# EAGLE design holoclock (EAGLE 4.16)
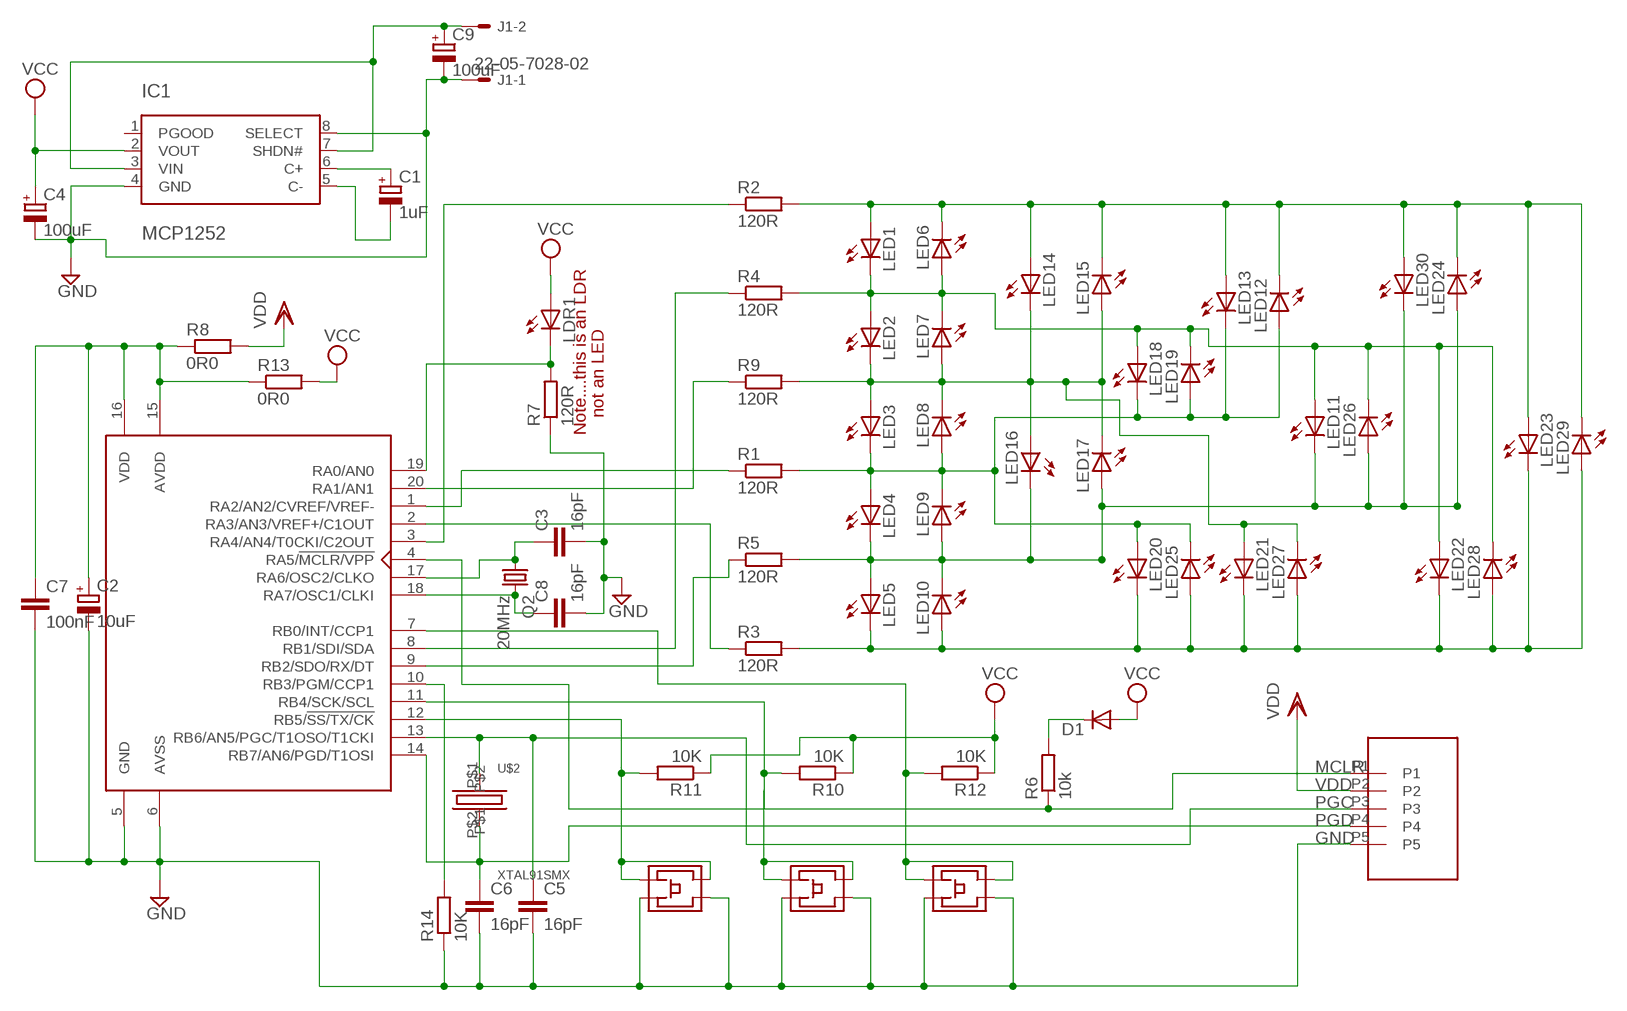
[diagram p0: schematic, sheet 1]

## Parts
C1  1uF  CPOL-EUSMCA  [SMC_A]
C2  10uF  CPOL-EUCT3528  [CT3528]
C3  16pF  C-EUC0805K  [C0805K]
C4  100uF  CPOL-EUSMCD  [SMC_D]
C5  16pF  C-EUC0805K  [C0805K]
C6  16pF  C-EUC0805K  [C0805K]
C7  100nF  C-EUC0805K  [C0805K]
C8  16pF  C-EUC0805K  [C0805K]
C9  100uF  CPOL-EUSMCD  [SMC_D]
D1  DIODE-MINIMELF  [MINIMELF]
IC1  MCP1252  [MSOP8]
J1  22-05-7028-02  [7395-02]
LDR1  LED5MM  [LED5MM]
LED1  LEDSMT1206  [1206]
LED2  LEDSMT1206  [1206]
LED3  LEDSMT1206  [1206]
LED4  LEDSMT1206  [1206]
LED5  LEDSMT1206  [1206]
LED6  LEDSMT1206  [1206]
LED7  LEDSMT1206  [1206]
LED8  LEDSMT1206  [1206]
LED9  LEDSMT1206  [1206]
LED10  LEDSMT1206  [1206]
LED11  LEDSMT1206  [1206]
LED12  LEDSMT1206  [1206]
LED13  LEDSMT1206  [1206]
LED14  LEDSMT1206  [1206]
LED15  LEDSMT1206  [1206]
LED16  LEDSMT1206  [1206]
LED17  LEDSMT1206  [1206]
LED18  LEDSMT1206  [1206]
LED19  LEDSMT1206  [1206]
LED20  LEDSMT1206  [1206]
LED21  LEDSMT1206  [1206]
LED22  LEDSMT1206  [1206]
LED23  LEDSMT1206  [1206]
LED24  LEDSMT1206  [1206]
LED25  LEDSMT1206  [1206]
LED26  LEDSMT1206  [1206]
LED27  LEDSMT1206  [1206]
LED28  LEDSMT1206  [1206]
LED29  LEDSMT1206  [1206]
LED30  LEDSMT1206  [1206]
Q2  20MHz  CRYSTALHC49UP  [HC49UP]
R1  120R  R-EU_M0805  [M0805]
R2  120R  R-EU_M0805  [M0805]
R3  120R  R-EU_M0805  [M0805]
R4  120R  R-EU_M0805  [M0805]
R5  120R  R-EU_M0805  [M0805]
R6  10k  R-EU_M0805  [M0805]
R7  120R  R-EU_M0805  [M0805]
R8  0R0  R-EU_M0805  [M0805]
R9  120R  R-EU_M0805  [M0805]
R10  10K  R-EU_M0805  [M0805]
R11  10K  R-EU_M0805  [M0805]
R12  10K  R-EU_M0805  [M0805]
R13  0R0  R-EU_M0805  [M0805]
R14  10K  R-EU_M0805  [M0805]
SW1  SMDMICROSWITCH  [SMDMICROSWITCH]
SW2  SMDMICROSWITCH  [SMDMICROSWITCH]
SW3  SMDMICROSWITCH  [SMDMICROSWITCH]
U$1  MATE-N-LOK-5WAY  [MATE-N-LOK-5WAY]
U$2  XTAL91SMX  [XTAL91SMX]
U$6  16F88SOIP20  [SSOP20]

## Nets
GND: C2.- C3.2 C4.- C5.2 C6.2 C7.2 C8.2 C9.- IC1.4(GND) IC1.8(SELECT) J1.1 R7.1 R14.1 SW1.L1 SW1.R1 SW2.L1 SW2.R1 SW3.L1 SW3.R1 U$1.P5 U$6.5(GND) U$6.6(AVSS)
LDR1: LDR1.K(C) R7.2 U$6.19(RA0/AN0)
MCLR: R6.1 U$1.P1 U$6.4(RA5/!MCLR/VPP)
N$1: C8.1 Q2.2 U$6.18(RA7/OSC1/CLKI)
N$2: R2.1 U$6.3(RA4/AN4/T0CKI/C2OUT)
N$3: C3.1 Q2.1 U$6.17(RA6/OSC2/CLKO)
N$4: C9.+ IC1.3(VIN) IC1.7(SHDN#) J1.2
N$5: R3.1 U$6.2(RA3/AN3/VREF+/C1OUT)
N$6: R1.1 U$6.1(RA2/AN2/CVREF/VREF-)
N$7: R14.2 U$6.10(RB3/PGM/CCP1)
N$8: R10.2 SW1.L2 SW1.R2 U$6.11(RB4/SCK/SCL)
N$9: D1.C R6.2
N$10: C1.+ IC1.6(C+)
N$11: C1.- IC1.5(C-)
N$13: R11.2 SW3.L2 SW3.R2 U$6.12(RB5/!SS/TX/CK)
N$17: R5.1 U$6.9(RB2/SDO/RX/DT)
N$20: R9.1 U$6.20(RA1/AN1)
N$21: R4.1 U$6.8(RB1/SDI/SDA)
N$23: R12.2 SW2.L2 SW2.R2 U$6.7(RB0/INT/CCP1)
PGC: C5.1 U$1.P3 U$2.P$1 U$6.13(RB6/AN5/PGC/T1OSO/T1CKI)
PGD: C6.1 U$1.P4 U$2.P$2 U$6.14(RB7/AN6/PGD/T1OSI)
PWRCPU: C2.+ C7.1 R8.1 R13.1 U$6.15(AVDD) U$6.16(VDD)
R1: LED1.A LED6.C LED12.C LED13.A LED14.A LED15.C LED23.A LED24.C LED29.C LED30.A R2.2
R2: LED1.C LED2.A LED6.A LED7.C LED11.A LED18.A LED19.C LED22.A LED26.C LED28.C R4.2
R3: LED2.C LED3.A LED7.A LED8.C LED14.C LED15.A LED16.A LED17.C LED21.A LED27.C R9.2
R4: LED3.C LED4.A LED8.A LED9.C LED12.A LED13.C LED18.C LED19.A LED20.A LED25.C R1.2
R5: LED4.C LED5.A LED9.A LED10.C LED11.C LED16.C LED17.A LED24.A LED26.A LED30.C R5.2
R6: LED5.C LED10.A LED20.C LED21.C LED22.C LED23.C LED25.A LED27.A LED28.A LED29.A R3.2
VCC: C4.+ D1.A IC1.2(VOUT) LDR1.A R10.1 R11.1 R12.1 R13.2
VDD: R8.2 U$1.P2
Unconnected: IC1.1(PGOOD)

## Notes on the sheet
- not an LED
- Note....this is an LDR

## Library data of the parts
C1 C2 C4 C9 = rcl:CPOL-EU: POLARIZED CAPACITOR, European symbol
C3 C5-C8 = rcl:C-EU: CAPACITOR, European symbol
D1 = diode:DIODE-: DIODE
IC1 = microchip-dspic:MCP1252: Positive-Regulated Charge Pump (3.3x5.0)
J1 = con-molex:22-?-02: CONNECTOR
LDR1 = custom:LED: LED
LED1-LED30 = led:LED: LED
Q2 = crystal:CRYSTAL: CRYSTAL
R1-R14 = rcl:R-EU_: RESISTOR, European symbol
SW1-SW3 = custom:SMDMICROSWITCH
U$1 = custom:MATE-N-LOK-5WAY
U$2 = custom:XTAL91SMX
U$6 = microchip:16F88SOIP20

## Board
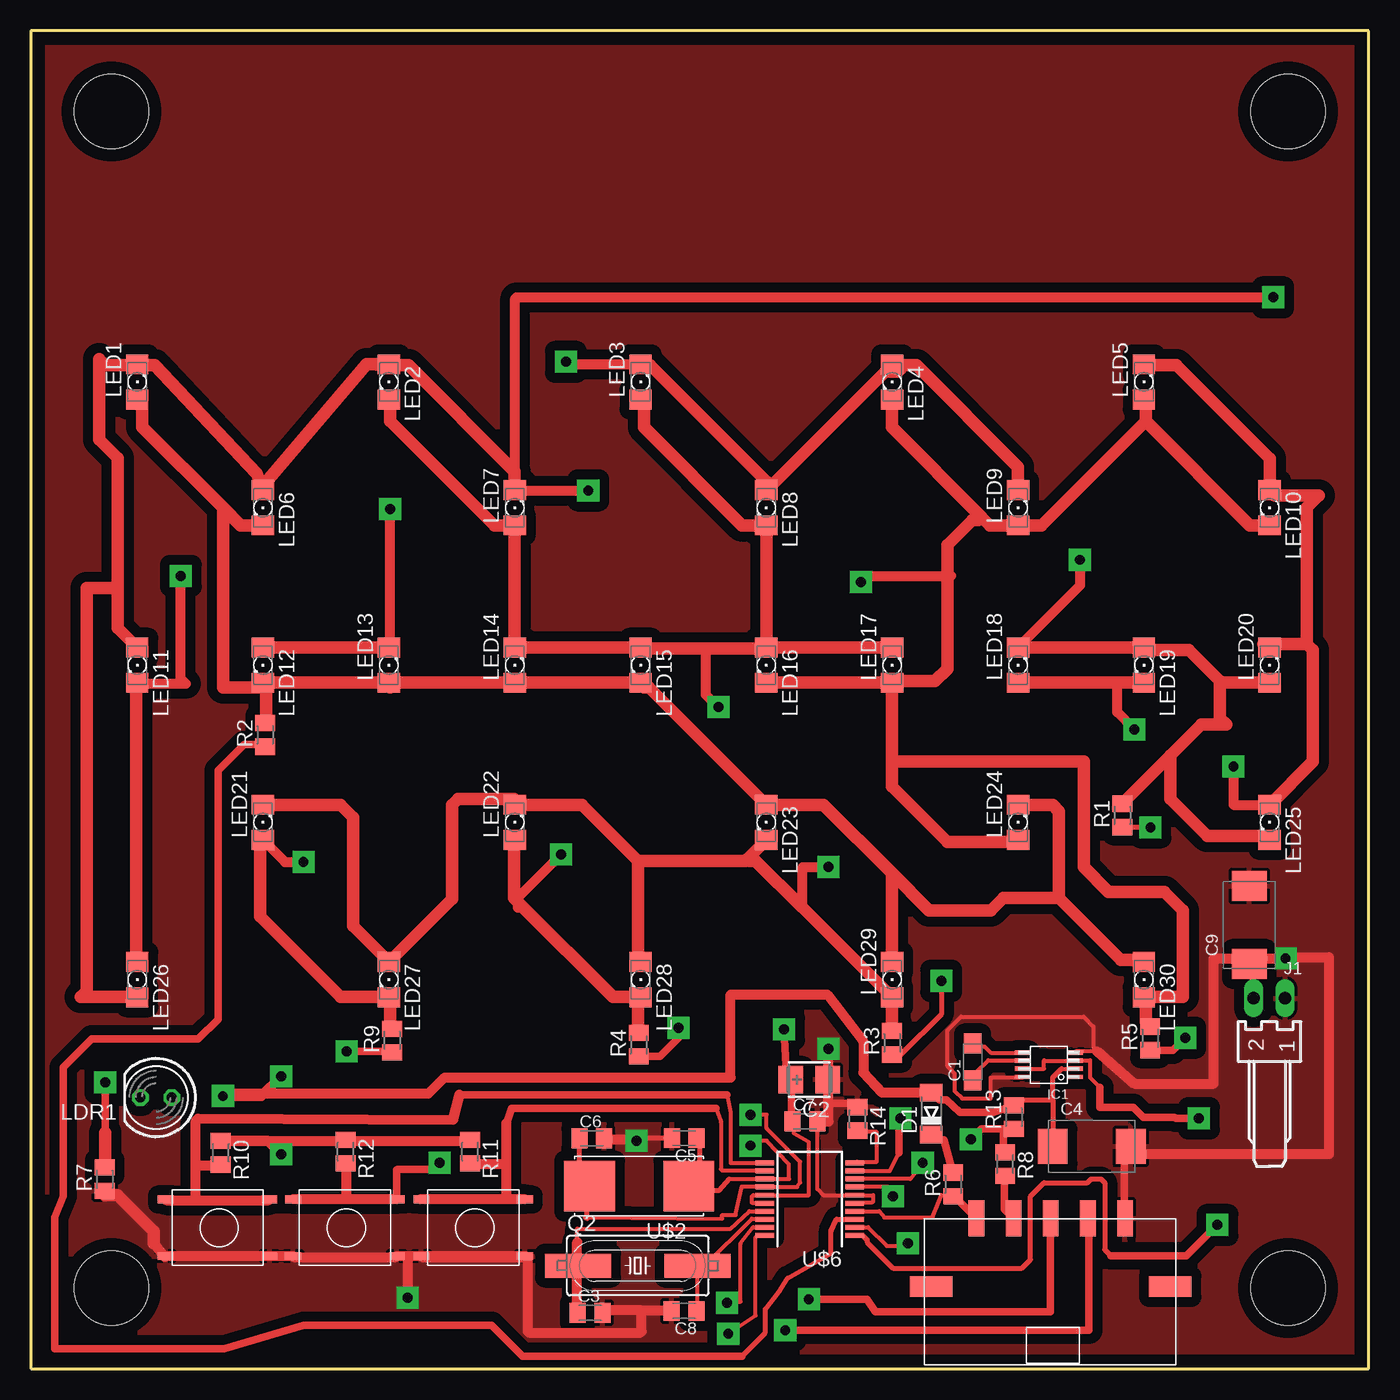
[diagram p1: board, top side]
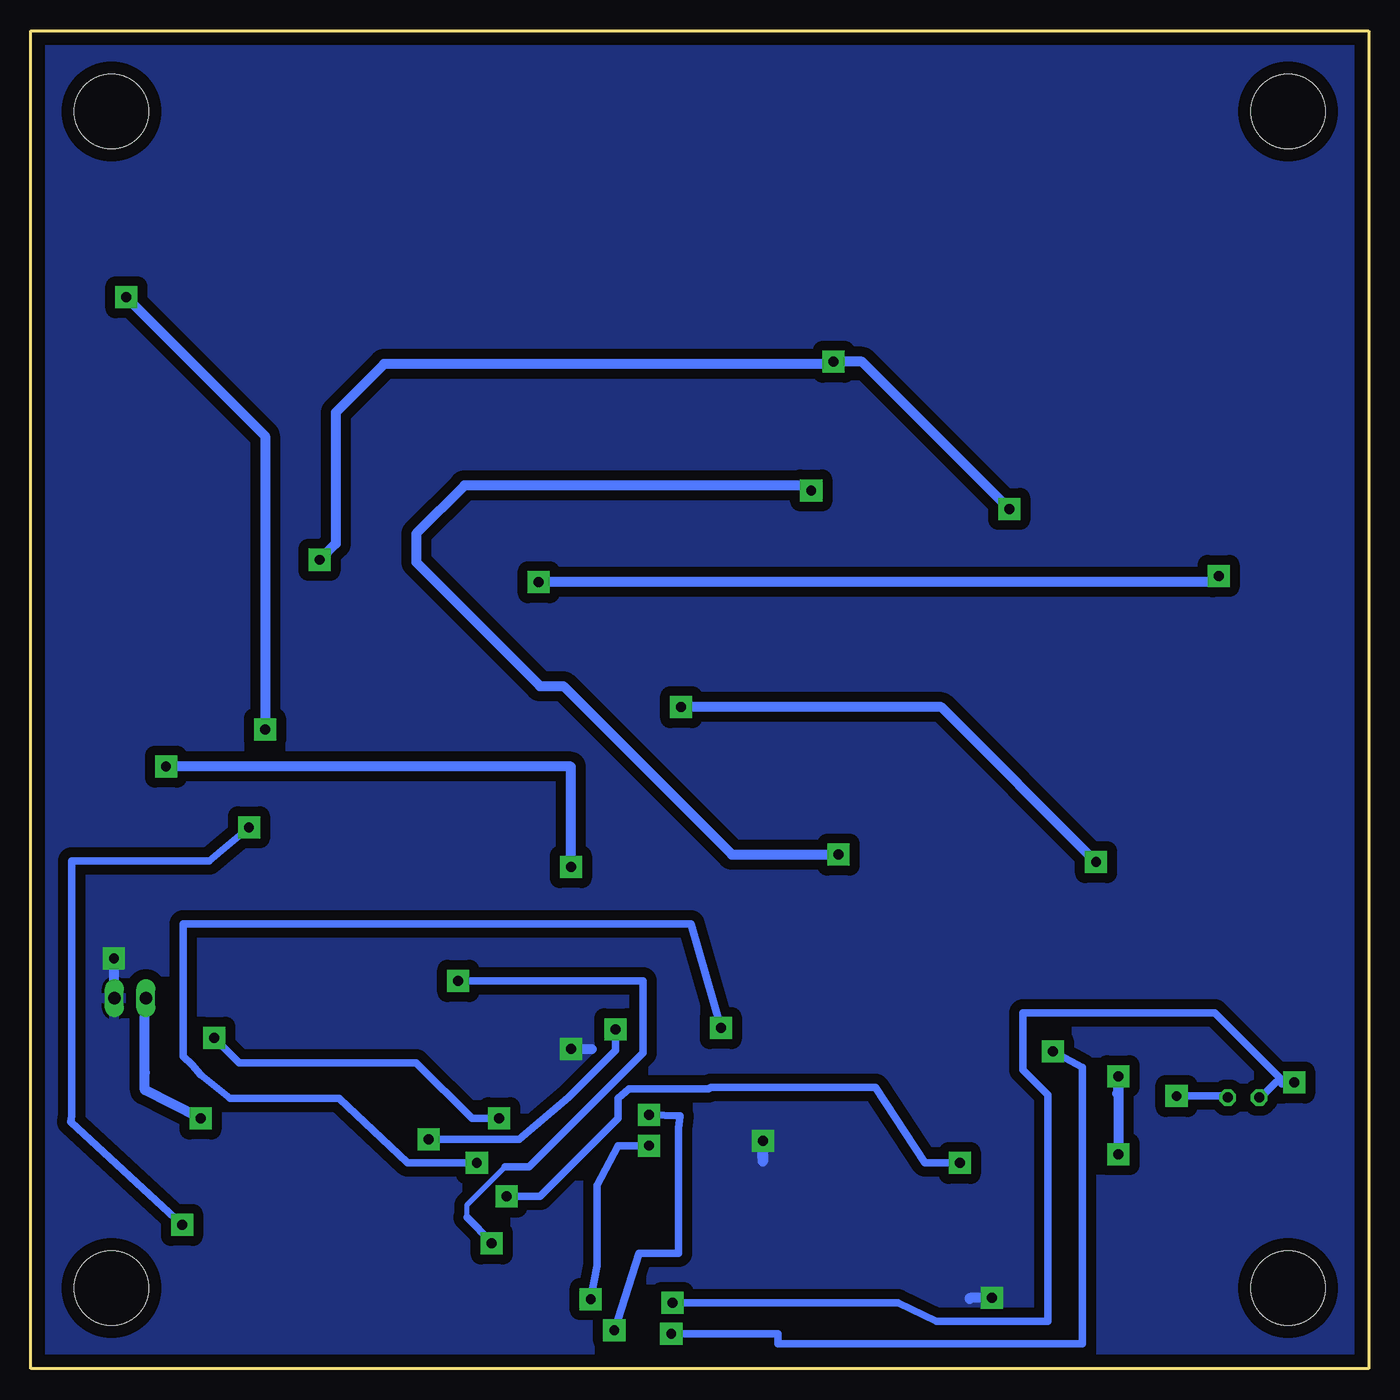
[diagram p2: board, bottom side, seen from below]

Size 108 x 108 mm. Coordinates in mm from the lower left corner, seen from the top.
Outline: 0,0 108,0 108,108 0,108 0,0
Copper layers (1*16): Top 0.035mm / dielectric 1.5mm / Bottom 0.035mm
Design rules "default": minimum track width 10mil, minimum drill 24mil, track to track 8mil, track to pad 8mil, pad to pad 8mil, via to via 8mil, smd to smd 8mil, copper to edge 40mil, drill to drill 8mil, minimum pad ring 10mil, minimum via ring 8mil, stop-mask expansion 4mil, vias tented up to drill 0mil, thermal gap 10mil
Holes 6 mm at 6.5,6.5 101.5,6.5 101.5,101.5 6.5,101.5

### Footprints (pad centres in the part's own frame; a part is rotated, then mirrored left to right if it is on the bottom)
SMC_A = smd 1.6 x 1.4: + -1.5,0; - 1.5,0
CT3528 = smd 2 x 2.2: + 1.5,0; - -1.5,0
C0805K = smd 1.3 x 1.6: 1 -1,0; 2 1,0
SMC_D = smd 2.4 x 2.8: + -3.15,0; - 3.15,0
MINIMELF = smd 1.4 x 1.8: A 1.7,0; C -1.7,0
MSOP8 = smd 1.2 x 0.35: 1 -2.145,0.975; 2 -2.145,0.325; 3 -2.145,-0.325; 4 -2.145,-0.975; 5 2.145,-0.975; 6 2.145,-0.325; 7 2.145,0.325; 8 2.145,0.975
7395-02 = drill 1.016 long: 1 1.27,0; 2 -1.27,0
LED5MM = drill 0.813 octagon: A -1.27,0; K 1.27,0
1206 = smd 1.6 x 1.803: A -1.422,0; C 1.422,0
HC49UP = smd 5.334 x 1.93: 1 -4.826,0; 2 4.826,0
M0805 = smd 1.3 x 1.6: 1 -0.95,0; 2 0.95,0
SMDMICROSWITCH = smd 1.27 x 0.635: L1 0,0; L2 0,4.572; R1 8.382,0; R2 8.382,4.572
MATE-N-LOK-5WAY = smd 3.43 x 1.67: M1 -9.65,-5.5; M2 9.65,-5.5 | smd 1.27 x 2.92: P1 -6,0; P2 -3,0; P3 0,0; P4 3,0; P5 6,0
XTAL91SMX = smd 4.1 x 4.1: P$1 -4,0; P$2 4,0
SSOP20 = smd 0.4 x 1.5: 1 -2.925,-3.625; 2 -2.275,-3.625; 3 -1.625,-3.625; 4 -0.975,-3.625; 5 -0.325,-3.625; 6 0.325,-3.625; 7 0.975,-3.625; 8 1.625,-3.625; 9 2.275,-3.625; 10 2.925,-3.625; 11 2.925,3.625; 12 2.275,3.625; 13 1.625,3.625; 14 0.975,3.625; 15 0.325,3.625; 16 -0.325,3.625; 17 -0.975,3.625; 18 -1.625,3.625; 19 -2.275,3.625; 20 -2.925,3.625

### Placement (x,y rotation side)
C1  76.03,24.76 90 top
C2  62.84,23.33 180 top
C3  45.14,4.5 0 top
C4  85.65,17.94 0 top
C5  52.75,18.61 180 top
C6  45.28,18.59 0 top
C7  62.5,19.95 0 top
C8  52.73,4.65 180 top
C9  98.38,35.82 90 top
D1  72.69,20.58 90 top
IC1  82.18,24.53 180 top
J1  99.99,29.9 0 top
LDR1  10.1,21.88 180 top
LED1  8.58,79.66 90 top
LED2  28.9,79.66 270 top
LED3  49.22,79.66 90 top
LED4  69.54,79.66 270 top
LED5  89.86,79.66 90 top
LED6  18.74,69.5 270 top
LED7  39.06,69.5 90 top
LED8  59.38,69.5 270 top
LED9  79.7,69.5 90 top
LED10  100.02,69.5 270 top
LED11  8.58,56.8 270 top
LED12  18.74,56.8 270 top
LED13  28.9,56.8 90 top
LED14  39.06,56.8 90 top
LED15  49.22,56.8 270 top
LED16  59.38,56.8 270 top
LED17  69.54,56.8 90 top
LED18  79.7,56.8 90 top
LED19  89.86,56.8 270 top
LED20  100.02,56.8 90 top
LED21  18.74,44.1 90 top
LED22  39.06,44.1 90 top
LED23  59.38,44.1 270 top
LED24  79.7,44.1 90 top
LED25  100.02,44.1 270 top
LED26  8.58,31.4 270 top
LED27  28.9,31.4 270 top
LED28  49.22,31.4 270 top
LED29  69.54,31.4 90 top
LED30  89.86,31.4 270 top
Q2  49,8.31 0 top
R1  88.12,44.66 90 top
R2  18.92,51.16 90 top
R3  69.53,26.3 90 top
R4  49.08,26.14 90 top
R5  90.36,26.66 90 top
R6  74.46,14.87 90 top
R7  5.95,15.29 90 top
R8  78.66,16.51 270 top
R9  29.16,26.49 90 top
R10  15.33,17.42 270 top
R11  35.45,17.52 270 top
R12  25.41,17.52 270 top
R13  79.36,20.3 90 top
R14  66.74,20.16 270 top
SW1  10.88,9.08 0 top
SW2  21.16,9.08 0 top
SW3  31.52,9.08 0 top
U$1  82.34,12.12 0 top
U$2  49.11,14.74 180 top
U$6  62.88,13.68 90 top

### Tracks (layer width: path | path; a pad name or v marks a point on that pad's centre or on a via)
GND  (via drill 0.8 pad 1.78)
  Top 0.305: IC1.8 80.09,23.5 77.5,23.5 77.5,21.8 75.2,21.8 74.6,22.4 74.6,23.8 74,24.4 74,27.3 75.1,28.4 85,28.4 85.8,27.6 85.8,25.9 86.1,25.6 84.33,25.6 | 84.33,25.6 84.4,25.5 | 84.33,25.6 IC1.4 | C6.2 46.27,18.5 | C5.2 51.74,18.5 | 51.8,4.7 51.78,4.7 C8.2 | 46.34,4.7 C3.2 | 40.1,3 40.2,2.9 | 49.2,2.9 49.3,3 | 10.8,9 SW1.L1 10.9,9.1 | 19.24,9.1 SW1.R1 19.28,9.1 | 21.14,9.1 SW2.L1 21.24,9 | 29.46,9 SW2.R1 29.56,9.1 | 31.6,9.1 31.54,9.1 SW3.L1 31.6,9 | 39.9,9 SW3.R1 40.1,8.88 | 64.3,23.37 64.3,23.4 | 64.3,23.37 C2.- | 64.3,23.37 64.3,21.4 64.3,20.75 C7.2 63.5,14.5 64,14 U$6.6 | 66.45,21.4 R14.1 | U$6.5 66.66,13.4 67.9,13.4 68,13.5 68,14 U$6.6 | U$6.6
  Top 0.406: C5.2 48.9,18.61 48.9,18.3
  Top 0.61: 88.3,12.08 88.3,12 | 88.3,12.08 U$1.P5 | C4.- 88.3,17.44 88.3,12.08 | 64.3,21.4 66.45,21.4
  Top 0.813: 86.1,25.6 89.1,23 95.5,23 95.5,33.1 v101.3,33.1 102,33.2 104.8,33.2 104.8,17.3 89.44,17.3 C4.- | 46.27,18.5 48.9,18.5 v48.9,18.4 48.9,18.3 49,18.4 | 49.3,4.7 46.34,4.7 | 49.3,4.7 51.78,4.7 | 40.2,2.9 49.2,2.9 | 49.3,3 49.3,4.7 | 9.9,10.1 10.8,9 | 10.9,9.1 19.24,9.1 | 19.28,9.1 21.14,9.1 | 21.24,9 29.46,9 | 29.56,9.1 31.54,9.1 | 31.6,9 39.9,9 | 40.1,8.88 40.1,3 | SW3.R1 30.4,9.08 v30.4,5.7 | C7.2 64.4,19.95 v64.4,25.8
  Top 1.016: 9.9,10.1 9.9,11.1 7,14 6,14 6,14.29 R7.1
  Bottom 0.813: J1.1 101.46,29.7 101.3,30.1 v101.3,33.1 | v30.4,5.7 32.2,5.7 32.2,5.6 | v64.4,25.8 62.7,25.8 | v48.9,18.4 48.9,16.7 49,18.5 48.9,18.5 v48.9,18.4
  pour Bottom (isolate 0.813): 0.6,107 107.4,107 107.4,0.4 0.7,0.4
  pour Top (isolate 0.813): 0.6,107.4 107.6,107.4 107.6,0.4 0.6,0.4 0.6,107.1
LDR1  (via drill 0.8 pad 1.78)
  Top 0.305: U$6.19 58.3,11.4 57.3,10.1 57.3,5.4 v56.2,5.3
  Top 0.61: 6,19.05 v6,23.1
  Top 1.016: R7.2 6,16.29 6,19.05
  Bottom 0.305: 8.8,21.8 8.83,21.83 LDR1.K | 7.5,23.1 7,23.1 6.8,23.1
  Bottom 0.61: v56.2,5.3 38,5.3 34.9,3.8 25.9,3.8 25.9,22.1 27.9,24.1 27.9,28.7 12.4,28.7 6.8,23.1 | 7.5,23.1 8.8,21.8 | 7,23.1 7,23 6.9,23.1 v6,23.1
MCLR
  Top 0.305: U$6.4 68.5,12.7 68.9,12.2 72.8,12.2 73.3,13.5 73.5,14 73.84,14 R6.1
  Top 0.61: R6.1 73.98,13.9 74.56,13.9 U$1.P1
N$1
  Top 0.305: U$6.18 59.21,12.1 58.2,12.1 54.4,8.3 53.82,8.3 | 53.82,8.3 53.8,8.3 | 53.82,8.3 Q2.2 53.8,8.28 53.8,4.58 | 53.8,4.58 53.8,4.5 | C8.1 53.8,4.58
N$2
  Top 0.406: U$6.3 65.06,12.05 64.6,11.1 64.6,9.3 61.1,7.3 60.4,6.2 59.3,4.8 59.3,2.9 57.4,1 | 18.6,50.4 18.79,50.21 R2.1
  Top 0.61: 57.4,1 39.7,1 37.2,3.5 22,3.5 15.6,1.6 1.9,1.6 1.9,12.2 2.6,13.9 2.6,24.3 4.9,26.6 13.5,26.6 15.1,28.2 15.1,48.3 17.2,50.4 18.6,50.4
N$3
  Top 0.305: U$6.17 58,12.7 56.5,11.3 44.1,11.3 44.1,10.2 | 44.1,8.3 Q2.1 44.1,8.24 | C3.1 44.1,4.54
  Top 0.813: 44.1,8.3 44.1,10.2 | 44.1,4.54 44.1,8.24
N$4  (via drill 0.8 pad 1.78)
  Top 0.305: 86.3,22.7 85.5,23.5 85.5,24.9 84.38,24.9 IC1.3 81.8,24.86 | IC1.7 81.8,24.2 81.8,24.86 | 81.8,24.86 81.8,24.9
  Top 0.406: 98.6,29.9 98.6,29.8 | J1.2 98.6,29.9 | C9.+ 98.6,32.67 98.6,29.9
  Top 0.61: v94.3,20.2 92.42,20.2 92.32,20.3 89.8,20.3 89,21.1 86.3,21.1 86.3,22.7
  Bottom 0.813: J1.2 98.82,28 98.8,23.9 98.8,22.5 v94.3,20.2
N$5  (via drill 0.8 pad 1.78)
  Top 0.305: U$6.2 67.59,11.4 69.1,9.9 70.6,9.9 v70.8,10.1
  Top 0.406: R3.1 69.53,25.37 69.5,25.4 70.3,25.4 73.5,28.6 v73.5,31.3
  Bottom 0.406: v70.8,10.1 70.8,10.2 | 72.8,12.2 72.8,13.2 69.7,16.3
  Bottom 0.61: 70.8,10.2 72.8,12.2 | 69.7,16.3 67.8,16.3 58.6,25.5 58.6,31.3 v73.5,31.3
N$6  (via drill 0.8 pad 1.78)
  Top 0.406: U$6.1 67.14,10.76 67.5,10.4 67.5,10.2 69.6,8.1 80,8.1 80.7,8.8 80.7,13.9 81.8,15 85.3,15 85.6,15.3 86.4,15.3 86.7,15 86.7,9.6 87.2,9.1 | R1.1 88.12,43.58 88.2,43.5 88.4,43.7 v90.4,43.7
  Top 0.61: 87.2,9.1 93.3,9.1 v95.8,11.6
  Bottom 0.61: v95.8,11.6 104.8,19.9 104.7,20.4 104.7,41 93.6,41 v90.4,43.7
N$7
  Top 0.305: U$6.10 66.71,16.7 68.3,16.7 68.3,19.1 66.85,19.1 R14.2
N$8
  Top 0.305: U$6.11 56.5,16.6 56.5,20.7 56.2,22.1 | 10.9,13.6 10.9,13.63 SW1.L2 | 19.21,13.6 SW1.R2
  Top 0.61: 34.6,22.1 56.2,22.1
  Top 0.813: 10.9,13.6 13.3,13.6 | 13.3,13.6 19.21,13.6 | 34.6,22.1 34.1,20.1 13.5,20.2 13.3,20 13.3,16.4 | 13.3,13.6 13.3,16.4 | R10.2 15.26,16.4 13.3,16.4
N$9
  Top 0.61: D1.C 73.21,18.5 73.3,18.5 73.7,18.46 R6.2
N$10
  Top 0.305: IC1.6 79.99,24.9 77.3,24.9 76.3,23.9 76.3,23.3 76.07,23.3 C1.+
N$11
  Top 0.305: IC1.5 77.5,25.5 77,26 76,26 76,26.23 C1.-
N$13
  Top 0.305: U$6.12 59.21,16 55.8,16 55.7,16.1 55.7,19.9 55.3,21 | 31.4,13.7 31.47,13.7 SW3.L2 | 39.85,13.7 SW3.R2 | 35.52,16.5 R11.2
  Top 0.61: 55.3,21 38.8,21 38.4,19.8
  Top 0.813: 31.47,13.7 38.4,13.7 | 38.4,13.7 39.85,13.7 | 38.4,13.7 38.4,16.5 | 38.4,16.5 38.4,19.8 | 38.4,16.5 35.52,16.5
N$14
  pour Bottom: 21.6,103.4 94.2,103.4 94.2,86.7 21.5,86.7 21.5,102.2
N$17  (via drill 0.8 pad 1.78)
  Top 0.305: U$6.9 69.36,15.96 70.1,17.4
  Top 0.61: 70.1,17.4 70.1,19.6 v70.2,20.2 | v93.2,26.7 92.2,25.7 90.5,25.7 90.49,25.71 R5.1
  Bottom 0.61: v70.2,20.2 72.4,20.2 76.9,24.7 91.2,24.7 v93.2,26.7
N$20  (via drill 0.8 pad 1.78)
  Top 0.305: U$6.20 58.66,10.76 58.5,10.6 58.5,4.3 v56.3,2.8 | 29.3,25.6 29.24,25.54 R9.1
  Top 0.61: v25.5,25.6 29.3,25.6
  Bottom 0.61: v56.3,2.8 47.7,2.8 47.7,2 23.1,2 23.1,24.3 v25.5,25.6
N$21  (via drill 0.8 pad 1.78)
  Top 0.305: U$6.8 71,15.3 v72,16.6 | 52.3,26.7 v52.3,27.5 | 49.11,25.19 49.3,25 49.5,25.2
  Top 0.61: 52.3,26.7 50.8,25.2 49.5,25.2 | R4.1 49.11,25.19
  Bottom 0.61: v72,16.6 77.6,16.6 83.1,21.8 91.9,21.8 94.3,23.7 95,24.5 95.7,25.2 95.7,35.9 54.7,35.9 v52.3,27.5
N$23  (via drill 0.8 pad 1.78)
  Top 0.305: 21.2,13.7 21.2,13.69 SW2.L2 | 29.49,13.7 SW2.R2 | U$6.7 69.25,14.65 v69.6,13.9
  Top 0.61: SW2.R2 29.54,16.04 29.6,16.1 32.5,16.1 v33,16.6
  Top 0.813: 21.2,13.7 25.5,13.7 | 25.5,13.7 29.49,13.7 | R12.2 25.5,16.48 25.5,13.7
  Bottom 0.61: v33,16.6 35.8,16.6 39.8,22.7 53.1,22.7 53.3,22.6 59.7,22.6 60.6,21.8 60.6,20.2 66.9,13.9 v69.6,13.9
PGC  (via drill 0.8 pad 1.78)
  Top 0.305: 56.4,15.3 U$6.13 61.2,15.3 61.2,15.4 61.2,16.5 59.4,18.4 58.5,18.4 v58.1,18 | U$1.P3 82.34,12.06 82.4,12 82.3,11.9
  Top 0.406: C5.1 54,18.61 54,14.5 | 54,14.5 54,14.4 55.6,14.4 56.4,15.3 | U$2.P$1 54,14.74 54,14.5
  Top 0.61: v62.8,5.6 67.5,5.6 68.2,4.6 82.3,4.6 82.3,11.9
  Bottom 0.61: v58.1,18 60.6,18 62.3,14.8 62.3,8.3 v62.8,5.6
PGD  (via drill 0.8 pad 1.78)
  Top 0.305: 44.77,12.2 55.8,12.1 55.8,12.4 56.9,12.4 57.4,14.7 59.1,14.7 U$6.14 61.85,14.65 62.1,15 62.1,16.7 59.4,19.4 59.4,20.5 v58.1,20.5 | 44.3,13.8 44.27,13.8 | 85.34,12.16 85.3,12.2 | 85.34,12.16 U$1.P4 | 85.4,12.1 85.34,12.16
  Top 0.406: C6.1 44.3,18.59 44.3,13.8 44.3,14.74 44.9,14.74 | 44.9,14.74 44.9,14.8 | 44.9,14.74 U$2.P$2 | 44.77,12.2 44.9,12.1 44.9,14.74
  Top 0.61: v60.9,3.1 85.4,3.1 85.4,12.1
  Bottom 0.61: v58.1,20.5 55.6,20.4 55.7,19.4 55.7,9.3 58.9,9.3 v60.9,3.1
PWRCPU  (via drill 0.8 pad 1.78)
  Top 0.305: U$6.16 59.21,13.4 58.2,13.4 58.2,13.9 58.3,14 U$6.15 62.8,14 62.8,18.3 61.6,19 61.6,19.85 C7.1 61.4,20.05 | 61.4,23.27 C2.+
  Top 0.61: 78.5,17.3 78.5,17.2 | 78.5,17.3 R8.1 | 78.5,17.3 78.5,19.31 R13.1 76.75,19.35 v75.9,18.5 | 61.4,20.05 61.4,23.27 | 61.37,23.33 61.4,23.3 | C2.+ 61.37,23.33 | v60.8,27.4 61,23.7 61.37,23.33
  Bottom 0.61: v75.9,18.5 68.6,18.5 64.6,21.9 60.8,25.7 v60.8,27.4
R1
  Top 1.016: LED6.C 16.92,68.08 15.5,69.5 | 15.5,69.5 9,76 9,77.5 8.5,78 8.58,78.08 LED1.A | LED15.C LED14.A 29.38,55.38 29,55 28.9,55.1 LED13.A 19.38,55.38 19,55 | LED15.C 49.38,55.38 49.5,55.5 | 19,55 18.74,55.26 LED12.C | LED12.C 18.36,55 15.5,55 15.5,69.5 | LED15.C 49.5,55.1 49.5,55 49.9,55 LED23.A 59.4,45.5 64,45.5 69.5,40 | 19,55 19,55.12 LED12.C | R2.2 19,52.19 19,55 | LED29.C 69.5,32.86 69.5,40 | LED24.C 79.72,45.5 82.5,45.5 83,45 83,38 | LED30.A 89.68,33 88,33 83,38 | 69.5,40 72.5,37 77.5,37 78.5,38 83,38
R2  (via drill 0.8 pad 1.78)
  Top 0.813: v100.3,86.5 39.2,86.5 39.1,86.4 39.1,70.96 LED7.C 39.08,70.9 v45,70.9 | v89.1,51.6 87.7,53 87.7,55.38 | 39.55,37.45 39.3,37.2 39.3,38 v42.8,41.5
  Top 1.016: LED7.C 39.06,72.44 30.5,81 28.5,81 27.08,81.08 | 27.08,81.08 LED2.A | 27.08,81.08 18.5,71 18.58,70.92 LED6.A 18.24,72.26 10,81 8.5,81 | 8.5,81 LED1.C 8.5,81 | 79.62,55.38 LED18.A | 79.62,55.38 87.7,55.38 LED19.C | 79.62,55.38 79.5,55.5 | LED11.A 7,59.8 7,63 | 7,63 7,73.5 5.5,75 5.5,81.5 6,81 8.5,81 | 49,30 47,30 39.55,37.45 39,38 39,42.62 LED22.A | 49,30 49.2,30 LED28.C | R4.2 49,27.17 49,30 | LED26.C 8.56,30 4,30 4.5,30.5 4.5,63 7,63
  Bottom 0.813: v100.3,86.5 89.1,75.3 v89.1,51.6 | v45,70.9 45.4,71.3 73,71.3 76.9,67.4 76.9,65.1 66.9,55.1 65,55.1 51.4,41.5 v42.8,41.5
R3  (via drill 0.8 pad 1.78)
  Top 0.813: LED21.A 20.52,40.9 v22,40.9 | v55.5,53.4 54.5,54.4 54.5,58.12
  Top 1.016: LED2.C 28.9,78.1 29,78 29,76.5 37.42,68.08 LED7.A 39.06,68.06 39,68 39.06,67.94 LED14.C 39.06,58.44 | LED3.A 49.26,78.24 49.5,78 49.5,76 57.42,68.08 LED8.C 59.42,68.08 59.5,68 59.38,67.88 LED16.A 59.38,58.12 | 59.38,58.12 59.5,58 59.72,58.22 LED17.C | 59.38,58.12 54.5,58.12 49.88,58.12 49.5,58.5 LED15.A 39.28,58.22 39.06,58.44 | 39.06,58.44 39,58.5 | R9.2 29,27.6 29,29.88 LED27.C 28.88,30 25,30 18.5,36.5 18.5,42.5 18.56,42.5 LED21.A
  Bottom 0.813: v22,40.9 34.5,53.4 v55.5,53.4
R4  (via drill 0.8 pad 1.78)
  Top 0.813: LED13.C 29,58.32 v29,69.4 | 49.24,81.1 49.5,81.1 | 49.24,81.1 LED3.C | v43.2,81.3 43.4,81.1 49.24,81.1 | LED18.C 84.7,63.22 v84.7,65.3
  Top 1.016: LED9.C 79.7,72.8 71.5,81 70.5,81 70,80.5 69.5,80.5 | LED4.A 69.54,81.04 69.5,81 69.5,80.5 | 69.5,80.5 69,80.5 59.42,70.92 LED8.A 59.38,71.62 50,81 49,81 49.08,81.08 LED3.C | LED20.A 96.12,55.38 96,55.5 | 96,55.5 93.5,58 90.5,58 90,58.5 89.86,58.36 LED19.A 80.22,58.22 80,58 79.78,58.22 LED18.C | 18.74,58.26 18.5,58.5 | LED12.A 18.74,58.26 | LED13.C 18.78,58.22 18.74,58.26 | 92,49.49 R1.2 | 92,49.49 94.51,52 96.5,52 96,52.5 96,55.5 | LED25.C 99.7,43 95,43 92,46 92,49.5 92,49.49
  Bottom 0.813: v29,69.4 40.9,81.3 v43.2,81.3 43.4,81.5 43.4,81.4 43.7,81.1 79.5,81.1 83.4,77.2 83.4,66.6 v84.7,65.3
R5  (via drill 0.8 pad 1.78)
  Top 0.813: LED11.C 8.66,55.3 12.5,55.3 12.1,55.7 v12.1,64 | 74.3,64 74,64 67.5,64 v67,63.5
  Top 1.016: 76.75,68.75 69.5,76 69.5,78 69.54,78.04 LED4.C | 76.75,68.75 77.42,68.08 LED9.A 81.58,68.08 90,76.5 | LED5.A 89.86,78.14 90,78 90,76.5 | LED10.C 98.42,68.08 90,76.5 | LED16.C 59.5,55.5 59.62,55.38 LED17.A | LED24.A 79.52,42.5 74,42.5 69.5,47 69.5,49 | LED17.A 69.5,55.34 69.5,49 | R5.2 90,27.97 90,29.84 LED30.C 89.88,30 93,30 93,37 91.5,38.5 87,38.5 85,40.5 85,49 69.5,49 | LED17.A 69.66,55.5 73,55.5 74,56.5 74,64 74,66.5 76,68.5 76.5,68.5 76.75,68.75 | LED11.C 8.5,55.3 8.5,32.9 LED26.A
  Bottom 0.813: v12.1,64 12.6,63.5 v67,63.5
R6  (via drill 0.8 pad 1.78)
  Top 0.813: LED25.A 97.1,45.52 v97.1,48.6 | 62.26,37.26 62.3,37.26 62.3,40.5 v64.4,40.5
  Top 1.016: LED5.C 89.92,81.08 90,81 92.5,81 100.02,73.48 LED10.A 100.44,70.5 104,70.5 103,69.5 103,58.5 | LED28.A 49,33.04 49,41 | 49,41 44.5,45.5 39.08,45.5 LED22.C 39,45.58 39,46 34.5,46 34,45.5 34,37.92 LED27.A 26,35.72 26,44.5 25,45.5 18.72,45.5 | 57.85,41.15 57.7,41 49,41 | 57.85,41.15 LED23.C | 18.72,45.5 18.5,45.5 | 18.72,45.5 LED21.C | R3.2 69.5,27.28 69.5,29.94 LED29.A 62.26,37.26 58.52,41 58,41 57.85,41.15 | LED25.A 103.5,49 103.5,58 103,58.5 | 103,58.5 100,58.5 | 100,58.5 100,58.24 LED20.C | 100,58.5 99.5,58.5
  Bottom 0.813: v97.1,48.6 64.4,48.6 v64.4,40.5
VCC  (via drill 0.8 pad 1.78)
  Top 0.305: IC1.2 83.2,24.2
  Top 0.406: 83.2,24.2 82.5,23.5 82.5,21.7 | 82.5,21.7 C4.+ | R13.2 78.91,21.7 82.5,21.7
  Top 0.61: R13.2 77.71,20.7 75,20.7 73.9,21.7 73.37,21.7 D1.A
  Top 0.813: 25.48,18.4 R12.1 | 15.36,18.4 R10.1 | 15.36,18.4 25.48,18.4 | R11.1 35.5,18.42 35.5,18.4 25.48,18.4 | D1.A 68.72,22.28 67.2,23.9 67.2,26.4 64.3,30.2 56.5,30.2 56.5,23.5 33.4,23.5 32.1,22.2 15.8,22.2 15.6,22 | v15.5,22 15.6,22 | 15.36,18.4 19.1,18.4 v20.2,17.3 | 15.6,22 18.6,22 v20.2,23.6
  Top 1.016: LDR1.A 11.49,22
  Bottom 0.61: LDR1.A 11.37,21.83 11.4,21.8 11.6,22 v15.5,22
  Bottom 0.813: 20.2,22.3 20.2,23.5 | 20.2,22.1 v20.2,17.3 | 20.2,22.1 20.2,22.3 | 20.2,22.3 20.3,22.2 | v20.2,23.6 20.2,22.1
VDD
  Top 0.61: R8.2 78.62,15.6 78.6,15.6 78.6,12.86 U$1.P2

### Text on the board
bRestrict: MiniDot Clock Version 2 | Copyright 2007 Philip Pulle | RGB Sunset Productions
